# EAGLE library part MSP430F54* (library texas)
MIXED SIGNAL MICROCONTROLLER Auto generated by make-symbol-device-package-bsdl.ulp Rev. 27 Source: www.ti.com .. msp430f5437.pdf
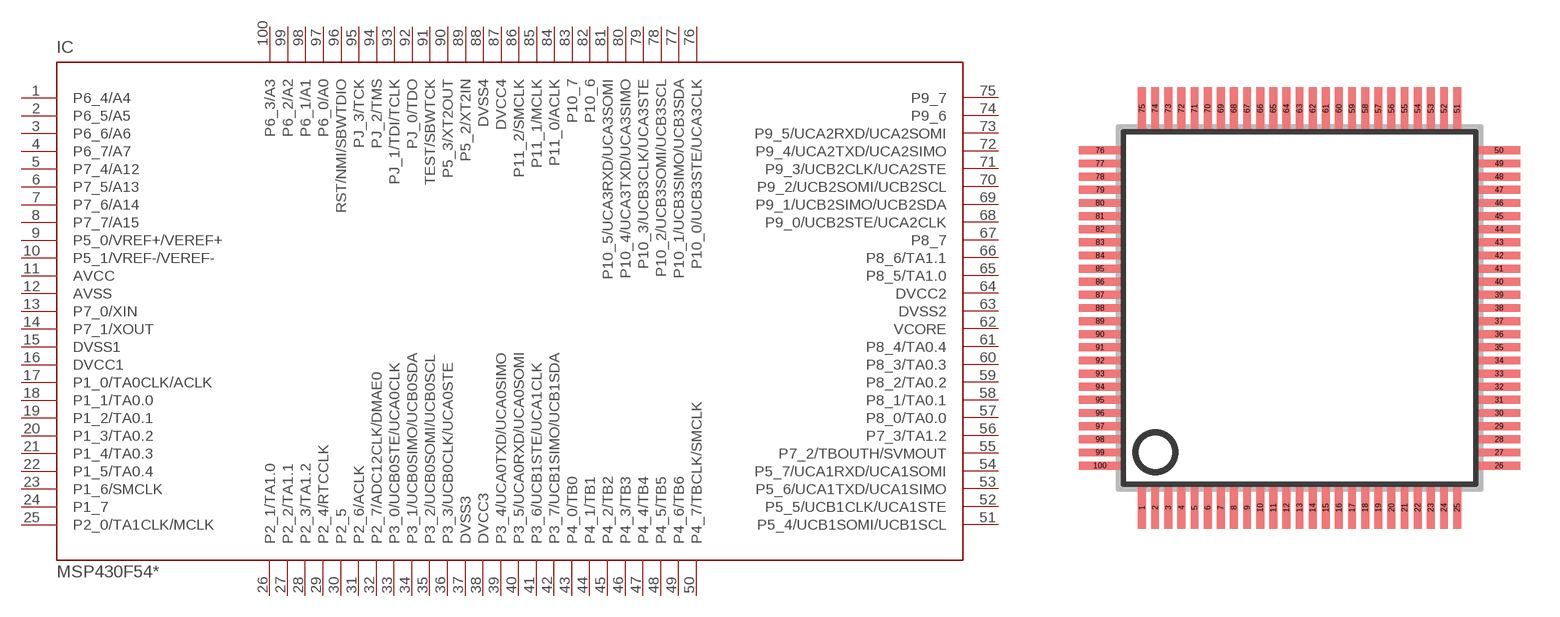
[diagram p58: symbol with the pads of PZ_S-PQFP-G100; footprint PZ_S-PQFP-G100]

Designator prefix IC

## MSP430F5419 (MPN: MSP430F5419IPZR; OC_FARNELL: 1740335; OC_NEWARK: 12P7733), MSP430F5419A (OC_FARNELL: unknown; OC_NEWARK: unknown), MSP430F5436 (MPN: MSP430F5436IPZ; OC_FARNELL: 1740338; OC_NEWARK: 86R1301), MSP430F5436A (MPN: MSP430F5436AIPZ; OC_FARNELL: 1740338; OC_NEWARK: 68R9298), MSP430F5438 (MPN: MSP430F5438IPZ; OC_FARNELL: 1740340; OC_NEWARK: 77R3126), MSP430F5438A (MPN: MSP430F5438AIPZ; OC_FARNELL: unknown; OC_NEWARK: 68R9304)  [PZ_S-PQFP-G100]
1  P6_4/A4
2  P6_5/A5
3  P6_6/A6
4  P6_7/A7
5  P7_4/A12
6  P7_5/A13
7  P7_6/A14
8  P7_7/A15
9  P5_0/VREF+/VEREF+
10  P5_1/VREF-/VEREF-
11  AVCC  pwr
12  AVSS  pwr
13  P7_0/XIN
14  P7_1/XOUT
15  DVSS1  pwr
16  DVCC1  pwr
17  P1_0/TA0CLK/ACLK
18  P1_1/TA0.0
19  P1_2/TA0.1
20  P1_3/TA0.2
21  P1_4/TA0.3
22  P1_5/TA0.4
23  P1_6/SMCLK
24  P1_7
25  P2_0/TA1CLK/MCLK
26  P2_1/TA1.0
27  P2_2/TA1.1
28  P2_3/TA1.2
29  P2_4/RTCCLK
30  P2_5
31  P2_6/ACLK
32  P2_7/ADC12CLK/DMAE0
33  P3_0/UCB0STE/UCA0CLK
34  P3_1/UCB0SIMO/UCB0SDA
35  P3_2/UCB0SOMI/UCB0SCL
36  P3_3/UCB0CLK/UCA0STE
37  DVSS3  pwr
38  DVCC3  pwr
39  P3_4/UCA0TXD/UCA0SIMO
40  P3_5/UCA0RXD/UCA0SOMI
41  P3_6/UCB1STE/UCA1CLK
42  P3_7/UCB1SIMO/UCB1SDA
43  P4_0/TB0
44  P4_1/TB1
45  P4_2/TB2
46  P4_3/TB3
47  P4_4/TB4
48  P4_5/TB5
49  P4_6/TB6
50  P4_7/TBCLK/SMCLK
51  P5_4/UCB1SOMI/UCB1SCL
52  P5_5/UCB1CLK/UCA1STE
53  P5_6/UCA1TXD/UCA1SIMO
54  P5_7/UCA1RXD/UCA1SOMI
55  P7_2/TBOUTH/SVMOUT
56  P7_3/TA1.2
57  P8_0/TA0.0
58  P8_1/TA0.1
59  P8_2/TA0.2
60  P8_3/TA0.3
61  P8_4/TA0.4
62  VCORE  pwr
63  DVSS2  pwr
64  DVCC2  pwr
65  P8_5/TA1.0
66  P8_6/TA1.1
67  P8_7
68  P9_0/UCB2STE/UCA2CLK
69  P9_1/UCB2SIMO/UCB2SDA
70  P9_2/UCB2SOMI/UCB2SCL
71  P9_3/UCB2CLK/UCA2STE
72  P9_4/UCA2TXD/UCA2SIMO
73  P9_5/UCA2RXD/UCA2SOMI
74  P9_6
75  P9_7
76  P10_0/UCB3STE/UCA3CLK
77  P10_1/UCB3SIMO/UCB3SDA
78  P10_2/UCB3SOMI/UCB3SCL
79  P10_3/UCB3CLK/UCA3STE
80  P10_4/UCA3TXD/UCA3SIMO
81  P10_5/UCA3RXD/UCA3SOMI
82  P10_6
83  P10_7
84  P11_0/ACLK
85  P11_1/MCLK
86  P11_2/SMCLK
87  DVCC4  pwr
88  DVSS4  pwr
89  P5_2/XT2IN
90  P5_3/XT2OUT
91  TEST/SBWTCK  in
92  PJ_0/TDO
93  PJ_1/TDI/TCLK
94  PJ_2/TMS
95  PJ_3/TCK
96  RST/NMI/SBWTDIO
97  P6_0/A0
98  P6_1/A1
99  P6_2/A2
100  P6_3/A3

## Footprint PZ_S-PQFP-G100 (pad centres in mm)
QFP100 Source: www.ti.com .. msp430f5437.pdf
smd 0.3 x 1.6: 1 -6,-7.6; 2 -5.5,-7.6; 3 -5,-7.6; 4 -4.5,-7.6; 5 -4,-7.6; 6 -3.5,-7.6; 7 -3,-7.6; 8 -2.5,-7.6; 9 -2,-7.6; 10 -1.5,-7.6; 11 -1,-7.6; 12 -0.5,-7.6; 13 0,-7.6; 14 0.5,-7.6; 15 1,-7.6; 16 1.5,-7.6; 17 2,-7.6; 18 2.5,-7.6; 19 3,-7.6; 20 3.5,-7.6; 21 4,-7.6; 22 4.5,-7.6; 23 5,-7.6; 24 5.5,-7.6; 25 6,-7.6; 51 6,7.6; 52 5.5,7.6; 53 5,7.6; 54 4.5,7.6; 55 4,7.6; 56 3.5,7.6; 57 3,7.6; 58 2.5,7.6; 59 2,7.6; 60 1.5,7.6; 61 1,7.6; 62 0.5,7.6; 63 0,7.6; 64 -0.5,7.6; 65 -1,7.6; 66 -1.5,7.6; 67 -2,7.6; 68 -2.5,7.6; 69 -3,7.6; 70 -3.5,7.6; 71 -4,7.6; 72 -4.5,7.6; 73 -5,7.6; 74 -5.5,7.6; 75 -6,7.6
smd 1.6 x 0.3: 26 7.6,-6; 27 7.6,-5.5; 28 7.6,-5; 29 7.6,-4.5; 30 7.6,-4; 31 7.6,-3.5; 32 7.6,-3; 33 7.6,-2.5; 34 7.6,-2; 35 7.6,-1.5; 36 7.6,-1; 37 7.6,-0.5; 38 7.6,0; 39 7.6,0.5; 40 7.6,1; 41 7.6,1.5; 42 7.6,2; 43 7.6,2.5; 44 7.6,3; 45 7.6,3.5; 46 7.6,4; 47 7.6,4.5; 48 7.6,5; 49 7.6,5.5; 50 7.6,6; 76 -7.6,6; 77 -7.6,5.5; 78 -7.6,5; 79 -7.6,4.5; 80 -7.6,4; 81 -7.6,3.5; 82 -7.6,3; 83 -7.6,2.5; 84 -7.6,2; 85 -7.6,1.5; 86 -7.6,1; 87 -7.6,0.5; 88 -7.6,0; 89 -7.6,-0.5; 90 -7.6,-1; 91 -7.6,-1.5; 92 -7.6,-2; 93 -7.6,-2.5; 94 -7.6,-3; 95 -7.6,-3.5; 96 -7.6,-4; 97 -7.6,-4.5; 98 -7.6,-5; 99 -7.6,-5.5; 100 -7.6,-6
